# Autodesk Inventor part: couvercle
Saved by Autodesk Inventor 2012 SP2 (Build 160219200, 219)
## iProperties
Created: 2013-04
Part Number: couvercle
Material: Default
Document SubType Name: Modeling
Designer: papa
Density: 1 g/cm^3
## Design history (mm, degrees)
node "couvercle1"
node "couvercle"
node "Base1"
